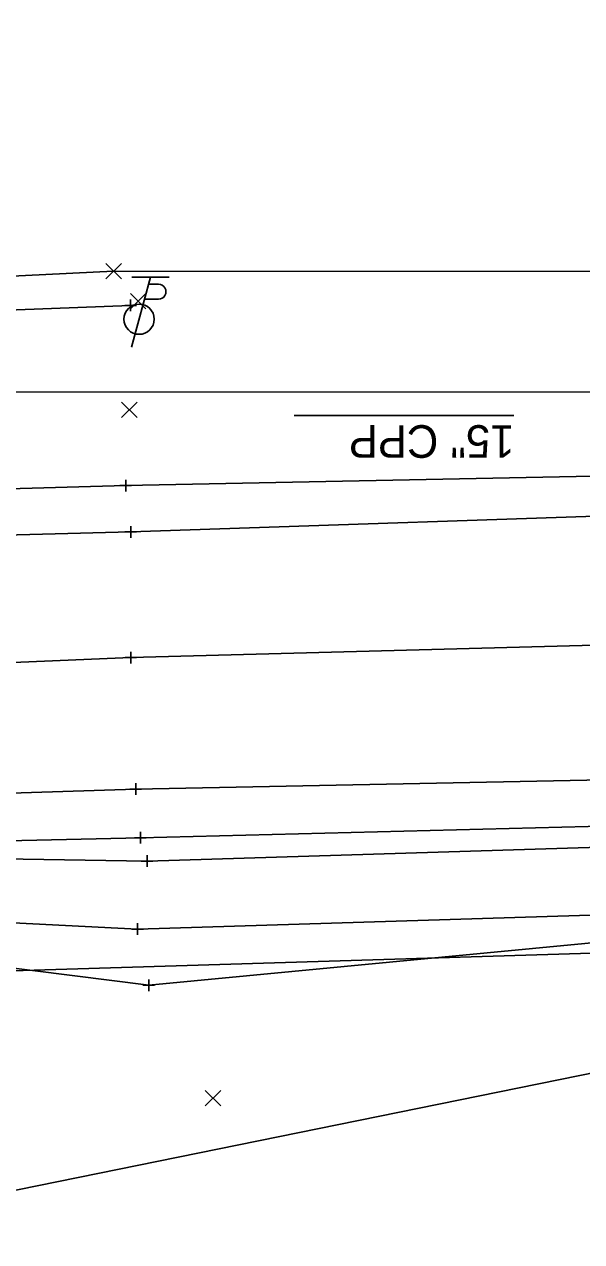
# Model space of a CAD drawing. Extents: x 2402028 to 2407435, y 498611 to 499105.
# Drawn here: x 2404076.7 to 2404124.6, y 498645 to 498749.5 of the extents above; entities that cross this region are included whole.
import ezdxf

# ---------------------------------------------------------------- set-up
doc = ezdxf.new("R2010")
doc.units = 0
for name, color, linetype in [('DR_X_Ditch', 7, 'Continuous'), ('DR_X_Storm_Sewer', 7, 'Continuous'), ('DR_X_Text', 7, 'Continuous'), ('PV_X_COP', 7, 'Continuous'), ('PV_X_EOP', 7, 'Continuous'), ('PV_X_Shoulder', 7, 'Continuous'), ('RW_X_CL_500_Bearings', 7, 'Continuous'), ('RW_X_CL_500_Cardinal_Points', 7, 'Continuous'), ('RW_X_CL_500_Stations', 7, 'Continuous'), ('SV_X_Break_Lines', 7, 'Continuous'), ('SV_X_Terrain_Boundary', 7, 'Continuous'), ('UT_X_Telecom', 7, 'Continuous')]:
    doc.layers.add(name, color=color, linetype=linetype)

msp = doc.modelspace()

# ---------------------------------------------------------------- linework, layer by layer
at = {"layer": 'DR_X_Ditch'}
msp.add_lwpolyline([(2404533.24, 498683.6), (2404485.13, 498682.32), (2404436.39, 498681.96), (2404386.54, 498679.04), (2404337.17, 498678.98), (2404287.56, 498677.96), (2404236.98, 498675.49), (2404187.96, 498674.52), (2404135.48, 498673.31), (2404086.4, 498671.8), (2404053.2, 498673.48), (2404047.02, 498674.14)], dxfattribs=at)
at = {"layer": 'DR_X_Storm_Sewer'}
msp.add_line((2404165.84, 498717.88), (2404056.73, 498717.91), dxfattribs=at)
at = {"layer": 'DR_X_Text'}
msp.add_line((2404099.85, 498715.87), (2404118.72, 498715.87), dxfattribs=at)
at = {"layer": 'PV_X_COP'}
msp.add_lwpolyline([(2403985.57, 498692.23), (2404036.54, 498693.02), (2404085.82, 498695.1), (2404135.38, 498696.42), (2404186.49, 498697.31), (2404235.26, 498698.66), (2404284.95, 498699.47), (2404334.96, 498700.99), (2404383.89, 498702.2), (2404434.73, 498703.18), (2404484.39, 498704.35), (2404533.55, 498705.6)], dxfattribs=at)
at = {"layer": 'PV_X_EOP'}
for points in [[(2403338.61, 498686.54), (2403387.34, 498688.53), (2403437.74, 498689.31), (2403487.06, 498690.99), (2403539.21, 498692.01), (2403587.62, 498693.45), (2403637.16, 498694.45), (2403686.98, 498695.6), (2403736.54, 498696.76), (2403786.79, 498698.23), (2403836.48, 498699.49), (2403886.02, 498700.75), (2403935.9, 498702.14), (2403985.32, 498703.46), (2404035.9, 498704.57), (2404085.81, 498705.89), (2404135.13, 498707.56), (2404185.41, 498708.59), (2404200.68, 498708.71)], [(2403985.56, 498681.24), (2404036.04, 498682.2), (2404086.24, 498683.82), (2404136.5, 498684.82), (2404187.36, 498686.15), (2404235.32, 498687.11), (2404285.36, 498688.37), (2404336.4, 498689.7), (2404384.93, 498690.9), (2404435.67, 498692.09), (2404485.01, 498693.22), (2404533.25, 498694.59)]]:
    msp.add_lwpolyline(points, dxfattribs=at)
at = {"layer": 'PV_X_Shoulder'}
for p, q in [((2404085.38, 498709.86), (2404134.88, 498710.88)), ((2404035.7, 498708.5), (2404085.38, 498709.86))]:
    msp.add_line(p, q, dxfattribs=at)
msp.add_lwpolyline([(2403986.56, 498676.91), (2404036.95, 498678.51), (2404086.64, 498679.64), (2404136.45, 498680.88), (2404187.63, 498682.62), (2404236.08, 498683.33), (2404286.33, 498684.49), (2404336.81, 498686.17), (2404385.43, 498687.48), (2404436.29, 498688.5), (2404485.75, 498689.82), (2404533.69, 498691.17)], dxfattribs=at)
at = {"layer": 'RW_X_CL_500_Bearings'}
for p, q in [((2404085.8, 498725.83), (2404085.8, 498724.83)), ((2404085.3, 498725.33), (2404086.3, 498725.33)), ((2404085.8, 498725.33), (2404085.8, 498725.33)), ((2404085.38, 498710.36), (2404085.38, 498709.36)), ((2404084.88, 498709.86), (2404085.88, 498709.86)), ((2404085.38, 498709.86), (2404085.38, 498709.86)), ((2404085.31, 498705.89), (2404086.31, 498705.89)), ((2404085.81, 498706.39), (2404085.81, 498705.39)), ((2404085.81, 498705.89), (2404085.81, 498705.89)), ((2404085.82, 498695.6), (2404085.82, 498694.6)), ((2404085.32, 498695.1), (2404086.32, 498695.1)), ((2404085.82, 498695.1), (2404085.82, 498695.1)), ((2404086.24, 498684.32), (2404086.24, 498683.32)), ((2404085.74, 498683.82), (2404086.74, 498683.82)), ((2404086.24, 498683.82), (2404086.24, 498683.82)), ((2404086.64, 498680.14), (2404086.64, 498679.14)), ((2404086.14, 498679.64), (2404087.14, 498679.64)), ((2404086.64, 498679.64), (2404086.64, 498679.64)), ((2404086.71, 498677.64), (2404087.71, 498677.64)), ((2404087.21, 498678.14), (2404087.21, 498677.14)), ((2404087.21, 498677.64), (2404087.21, 498677.64)), ((2404085.9, 498671.8), (2404086.9, 498671.8)), ((2404086.4, 498672.3), (2404086.4, 498671.3)), ((2404086.4, 498671.8), (2404086.4, 498671.8)), ((2404087.36, 498667.47), (2404087.36, 498666.47)), ((2404086.86, 498666.97), (2404087.86, 498666.97)), ((2404087.36, 498666.97), (2404087.36, 498666.97))]:
    msp.add_line(p, q, dxfattribs=at)
at = {"layer": 'RW_X_CL_500_Cardinal_Points'}
for p, q in [((2404087.5, 498727.75), (2404085.89, 498721.75)), ((2404089.1, 498727.75), (2404085.9, 498727.75)), ((2404087.34, 498727.15), (2404088.19, 498727.15)), ((2404086.99, 498725.87), (2404088.19, 498725.87))]:
    msp.add_line(p, q, dxfattribs=at)
msp.add_circle((2404086.53, 498724.15), 1.3, dxfattribs=at)
msp.add_arc((2404088.2, 498726.51), 0.638, 268.8767, 91.1233, dxfattribs=at)
at = {"layer": 'RW_X_CL_500_Stations'}
for p, q in [((2404083.68, 498727.61), (2404085.01, 498728.94)), ((2404083.68, 498728.94), (2404085.01, 498727.61)), ((2404085.78, 498725.03), (2404087.11, 498726.36)), ((2404085.78, 498726.36), (2404087.11, 498725.03)), ((2404085.03, 498715.7), (2404086.37, 498717.03)), ((2404085.03, 498717.03), (2404086.37, 498715.7)), ((2404092.22, 498656.62), (2404093.55, 498657.95)), ((2404092.22, 498657.95), (2404093.55, 498656.62))]:
    msp.add_line(p, q, dxfattribs=at)
at = {"layer": 'SV_X_Break_Lines'}
for points in [[(2404534.29, 498688.61), (2404486.42, 498687.58), (2404437.42, 498686.5), (2404385.81, 498685.86), (2404336.79, 498684.01), (2404286.16, 498682.85), (2404233.91, 498680.95), (2404188.17, 498680.27), (2404137.24, 498679.18), (2404087.21, 498677.64), (2404055.25, 498678.14)], [(2404534.06, 498678.67), (2404487.14, 498679.19), (2404435.91, 498680.7), (2404386.18, 498676.8), (2404335.53, 498673.1), (2404285.8, 498675.24), (2404235.32, 498670.62), (2404187.68, 498672.55), (2404137.13, 498671.73), (2404087.36, 498666.97), (2404054.4, 498671.14), (2404059.39, 498667.3)]]:
    msp.add_lwpolyline(points, dxfattribs=at)
at = {"layer": 'SV_X_Terrain_Boundary'}
for points in [[(2404243.83, 498747.15), (2404234.24, 498749.33), (2404224.02, 498749.46), (2404209.73, 498748.79), (2404134.41, 498728.23), (2404084.34, 498728.27), (2404013.92, 498724.8), (2403983.78, 498725.5)], [(2403985.55, 498656.18), (2404071.93, 498644.97), (2404075.01, 498646.62), (2404074.36, 498649.06), (2404127.78, 498659.91), (2404178.06, 498661.8), (2404232.73, 498665.07), (2404291.58, 498664.1)]]:
    msp.add_lwpolyline(points, dxfattribs=at)
at = {"layer": 'UT_X_Telecom'}
for points in [[(2404085.8, 498725.33), (2403922.2, 498719.12)], [(2404196.79, 498671.91), (2404031.46, 498666.86)]]:
    msp.add_lwpolyline(points, dxfattribs=at)

# ---------------------------------------------------------------- texts
at = {"layer": 'DR_X_Text'}
msp.add_text('15" CPP', height=2.8, rotation=179.9879, dxfattribs=at).set_placement((2404118.78, 498715.05))

doc.saveas('drawing.dxf')
